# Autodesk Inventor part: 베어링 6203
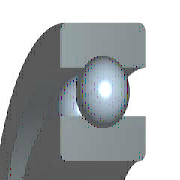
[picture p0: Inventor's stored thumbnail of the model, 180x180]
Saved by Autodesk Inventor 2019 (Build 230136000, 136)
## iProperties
IsCustomPart: 0
Created: 2014-10
Part Number: 베어링 6203
Material: 강철, 연강
Description: 깊은 그루브 볼 베어링
Document SubType Name: Modeling
Standard: KS B 2023
Designer: KYOUNG IL JANG
Standards Organization: KS
Language: ko-KR
Size Designation: 6203 - 17 x 40 x 12
Categories: <MemberInstance><Categories><Category DisplayName="샤프트 부품" InternalName="7f7aeb1f-a693-4053-b835-cee3144e0d98" Mnemonic="SHFT"><Category DisplayName="베어링" Inter
Density: 7.86 g/cm^3
Mass: 64.9809 g
Surface Area: 64.3582 cm^2
Volume: 8.26729 cm^3
Appearance: 노란색
Author: SeoGD™ [www.esajin.kr]
Revision Number: 1
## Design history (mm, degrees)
sketch "스케치" dims "d0" = 5.98 (= -0.26 x WD + 0.26 x BD)
  geometry: L1 (3.01, 14.25)-(8.99, 14.25); L2 (6, 14.25)-(6, 11.26); L3 (6, 14.25)-(6, 17.24); L4 (3.778, 12.249)-(0, 12.249); L5 (0, 8.5)-(12, 8.5); L6 (3.778, 16.251)-(0, 16.251); L7 (0, 20)-(12, 20); L8 (12, 8.5)-(12, 12.249); L9 (8.222, 12.249)-(12, 12.249); L10 (8.222, 16.251)-(12, 16.251); L11 (12, 20)-(12, 16.251); L12 (-1.4, 0)-(8.4, 0) reference; L13 (0, -0.3)-(0, 5.3) reference
  constraints: 22 end point, 4 point on line, 2 collinear, 2 perpendicular, 2 symmetric about line, 1 midpoint, 1 parallel, 14 other
  dimensions: "d9" = 17 diameter of L5 L12 (= WD); "d11" = 40 diameter of L7 L12 (= BD); "d12" = 12 distance between parallel lines of L8 L13 (= KB); "d13" = 24.498 diameter of L9 L12 (= 0.326 x BD + 0.674 x WD)
revolve "본체" stored, may be unused: angle "d6" = 90 deg
revolve "볼" stored, may be unused: angle "d7" = 90 deg
pattern_circular "IDS_ARRAYBALL[SIMPL:T]" dims angle "d3" = 360 deg
body "Solid1"
fillet "모깎기1" dims "d1" = 0.6 (= KRS)
other parameters: "WD" = 17 [user parameter; used in 5 equation terms], "BD" = 40 [user parameter; used in 5 equation terms], "KB" = 12 [user parameter; used in 1 equation term], "KRS" = 0.6 [user parameter; used in 1 equation term], "d4" = 0, "d5" = 0, "d8" = 0, "d14" = 0, "d15" = 0, "BBA" = 0 [user parameter], "BC0" = 4750000 [user parameter], "BC" = 9560000 [user parameter], "WR" = 8.5 (= 0.5 x WD) [user parameter]
